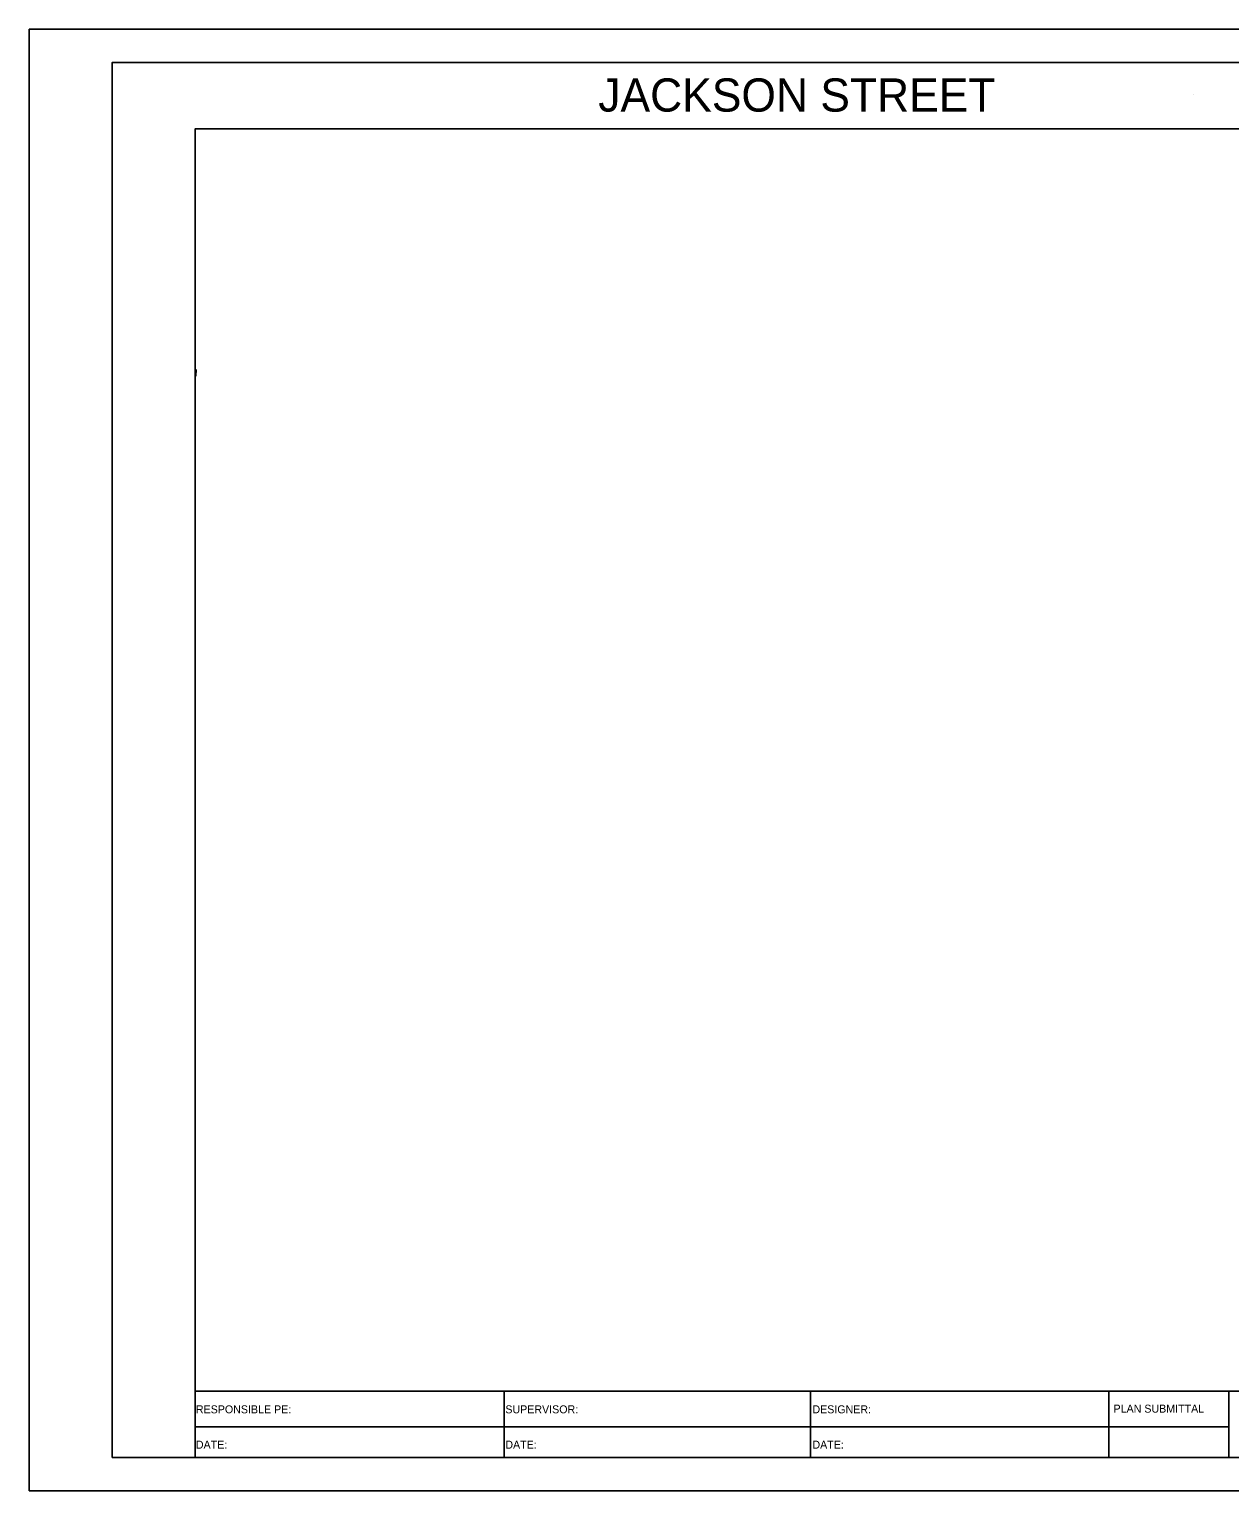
# Model space of a CAD drawing. Extents: x 1797478 to 1802796, y 246529 to 250952.
# Drawn here: x 1802116 to 1802296.8, y 250064.4 to 250284.4 of the extents above; entities that cross this region are included whole.
import ezdxf

# ---------------------------------------------------------------- set-up
doc = ezdxf.new("R2010")
doc.units = 0
for name, color, linetype in [('2', 7, 'Continuous'), ('ANNO-SHT', 7, 'Continuous'), ('ANNO-TXT', 7, 'Continuous'), ('AXIS', 7, 'Continuous'), ('DRAINAGE', 7, 'Continuous'), ('Level 1', 7, 'Continuous'), ('Level 62', 7, 'Continuous'), ('SHT-BDR', 7, 'Continuous'), ('SHT-BNDRY', 7, 'Continuous')]:
    doc.layers.add(name, color=color, linetype=linetype)

# ---------------------------------------------------------------- blocks, each defined once
blk = doc.blocks.new('SC47208')
at = {"layer": 'Level 1'}
blk.add_line((0, 0), (0, 0), dxfattribs=at)

msp = doc.modelspace()

# ---------------------------------------------------------------- linework, layer by layer
at = {"layer": '2'}
msp.add_lwpolyline([(1802141.12, 250233.21), (1802141.1, 250232.21)], dxfattribs=at)
msp.add_lwpolyline([(1802141.12, 250233.21), (1802141.1, 250232.21)], dxfattribs=at)
at = {"layer": 'AXIS'}
msp.add_line((1802141, 250189.42), (1802141, 250189.43), dxfattribs=at)
at = {"layer": 'Level 62'}
msp.add_lwpolyline([(1802116, 250064.42), (1802456, 250064.42), (1802456, 250284.42), (1802116, 250284.42)], close=True, dxfattribs=at)
at = {"layer": 'SHT-BDR'}
msp.add_lwpolyline([(1802141, 250079.43), (1802441, 250079.43), (1802441, 250269.43), (1802141, 250269.43)], close=True, dxfattribs=at)
at = {"layer": 'SHT-BNDRY'}
for p, q in [((1802141, 250069.42), (1802141, 250079.43)), ((1802187.52, 250079.43), (1802187.52, 250069.42)), ((1802233.67, 250069.42), (1802233.67, 250079.43)), ((1802278.59, 250069.42), (1802278.59, 250079.43)), ((1802296.63, 250069.42), (1802296.63, 250079.43)), ((1802141, 250074.03), (1802296.63, 250074.03))]:
    msp.add_line(p, q, dxfattribs=at)
msp.add_lwpolyline([(1802128.5, 250069.42), (1802451, 250069.42), (1802451, 250279.42), (1802128.5, 250279.42)], close=True, dxfattribs=at)

# ---------------------------------------------------------------- block references
at = {"layer": 'DRAINAGE', "xscale": 0.2, "yscale": 0.20000000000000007, "rotation": -116.41666666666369}
msp.add_blockref('SC47208', (1802291.32, 250274.62), dxfattribs=at)
msp.add_blockref('SC47208', (1802291.32, 250274.62), dxfattribs=at)

# ---------------------------------------------------------------- texts
at = {"layer": 'ANNO-SHT'}
msp.add_text('             JACKSON STREET             ', height=4.9995, rotation=360, dxfattribs=at).set_placement((1802177.55, 250272.02))
at = {"layer": 'ANNO-TXT'}
for s, p in [('RESPONSIBLE PE:', (1802141.1, 250076.08)), ('SUPERVISOR:', (1802187.7, 250076.08)), ('DESIGNER:', (1802233.94, 250076.08)), ('PLAN SUBMITTAL', (1802279.28, 250076.18)), ('DATE:', (1802141.1, 250070.76)), ('DATE:', (1802187.7, 250070.76)), ('DATE:', (1802233.94, 250070.76))]:
    msp.add_text(s, height=1.2, rotation=360, dxfattribs=at).set_placement(p)

doc.saveas('drawing.dxf')
